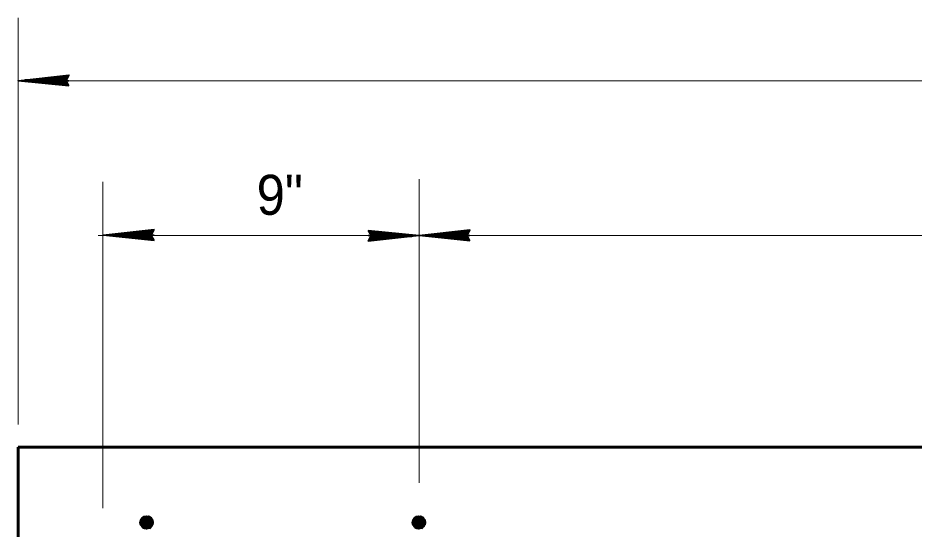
# Model space of a CAD drawing. Extents: x 6.34 to 9.53, y -1.46 to 0.53.
# Drawn here: x 6.7189 to 6.9057, y 0.195 to 0.3015 of the extents above; entities that cross this region are included whole.
import ezdxf
from ezdxf.enums import TextEntityAlignment as Align

# ---------------------------------------------------------------- set-up
doc = ezdxf.new("R2010")
doc.units = 0
doc.header["$LTSCALE"] = 0.0033
doc.layers.add('1', color=7, linetype='Continuous', lineweight=40)

msp = doc.modelspace()

# ---------------------------------------------------------------- linework, layer by layer
at = {"layer": '1', "lineweight": 13}
for p, q in [((6.718917, 0.216833), (6.718917, 0.3015)), ((6.718833, 0.288417), (7.301167, 0.288417)), ((6.736583, 0.199417), (6.736583, 0.267333)), ((6.8025, 0.204667), (6.8025, 0.267917)), ((6.735583, 0.256167), (7.2825, 0.256167)), ((6.718917, 0.212083), (6.718917, 0.212167))]:
    msp.add_line(p, q, dxfattribs=at)
at = {"layer": '1', "lineweight": 35}
for p, q in [((6.7295, 0.288417), (6.718917, 0.288417)), ((6.72925, 0.287583), (6.721417, 0.288583)), ((6.72925, 0.287583), (6.721417, 0.288417)), ((6.72925, 0.287417), (6.721417, 0.288333)), ((6.72925, 0.287417), (6.721417, 0.288333)), ((6.72925, 0.2875), (6.721417, 0.288333)), ((6.72925, 0.2895), (6.721917, 0.288667)), ((6.72925, 0.289333), (6.721917, 0.288583)), ((6.72925, 0.28925), (6.721917, 0.288417)), ((6.729333, 0.289083), (6.722, 0.288333)), ((6.74725, 0.25625), (6.736667, 0.25625)), ((6.747, 0.255417), (6.739167, 0.256417)), ((6.747, 0.255417), (6.739167, 0.25625)), ((6.747, 0.25525), (6.739167, 0.256167)), ((6.747, 0.25525), (6.739167, 0.256167)), ((6.747, 0.255333), (6.739167, 0.256167)), ((6.747, 0.257333), (6.739667, 0.2565)), ((6.747, 0.257167), (6.739667, 0.256417)), ((6.747, 0.257083), (6.739667, 0.25625)), ((6.747083, 0.256917), (6.73975, 0.256167)), ((6.791917, 0.256167), (6.8025, 0.256167)), ((6.792083, 0.2555), (6.799417, 0.25625)), ((6.792167, 0.257167), (6.8, 0.25625)), ((6.792167, 0.257167), (6.8, 0.25625)), ((6.792167, 0.257083), (6.8, 0.25625)), ((6.792167, 0.257), (6.8, 0.256167)), ((6.792167, 0.257), (6.8, 0.256)), ((6.792167, 0.255333), (6.7995, 0.256167)), ((6.792167, 0.25525), (6.7995, 0.256)), ((6.813083, 0.256167), (6.8025, 0.256167)), ((6.812833, 0.255333), (6.805, 0.256333)), ((6.812833, 0.255333), (6.805, 0.256167)), ((6.812833, 0.255167), (6.805, 0.256083)), ((6.812833, 0.255167), (6.805, 0.256083)), ((6.812833, 0.25525), (6.805, 0.256083)), ((6.812833, 0.25725), (6.8055, 0.256417)), ((6.812833, 0.257083), (6.8055, 0.256333)), ((6.812833, 0.257), (6.8055, 0.256167)), ((6.812917, 0.256833), (6.805583, 0.256083)), ((6.792167, 0.255083), (6.7995, 0.255917))]:
    msp.add_line(p, q, dxfattribs=at)
at = {"layer": '1', "lineweight": 60}
msp.add_line((6.718917, 0.212083), (7.30225, 0.212083), dxfattribs=at)
at = {"layer": '1'}
for p, q in [((6.74475, 0.195583), (6.745083, 0.1975)), ((6.744917, 0.1955), (6.74525, 0.1975)), ((6.744917, 0.1965), (6.746417, 0.196417)), ((6.744917, 0.196417), (6.746417, 0.196333)), ((6.744917, 0.196333), (6.746417, 0.19625)), ((6.744917, 0.19625), (6.746417, 0.196167)), ((6.744917, 0.196167), (6.746417, 0.196083)), ((6.745, 0.197583), (6.7465, 0.1975)), ((6.745, 0.1955), (6.745333, 0.1975)), ((6.745, 0.197417), (6.7465, 0.197333)), ((6.745, 0.197333), (6.7465, 0.19725)), ((6.745, 0.19725), (6.7465, 0.197167)), ((6.745, 0.197167), (6.7465, 0.197083)), ((6.745, 0.197083), (6.7465, 0.197)), ((6.745, 0.197), (6.7465, 0.196917)), ((6.745, 0.196917), (6.7465, 0.196833)), ((6.745, 0.196917), (6.7465, 0.196833)), ((6.745, 0.196833), (6.7465, 0.196667)), ((6.745, 0.196667), (6.7465, 0.1965)), ((6.745083, 0.1955), (6.7455, 0.1975)), ((6.745167, 0.1955), (6.745583, 0.1975)), ((6.745333, 0.1955), (6.745667, 0.197417)), ((6.745417, 0.195417), (6.74575, 0.197417)), ((6.7455, 0.195417), (6.745917, 0.197417)), ((6.745583, 0.195417), (6.746, 0.197333)), ((6.745667, 0.195417), (6.746083, 0.197333)), ((6.745833, 0.195333), (6.74625, 0.197333)), ((6.746083, 0.195333), (6.746417, 0.197333)), ((6.746167, 0.195333), (6.7465, 0.19725)), ((6.74625, 0.195333), (6.746583, 0.19725)), ((6.746333, 0.19525), (6.746667, 0.19725)), ((6.8015, 0.195583), (6.801833, 0.1975)), ((6.801667, 0.1955), (6.802, 0.1975)), ((6.801667, 0.1965), (6.803167, 0.196417)), ((6.801667, 0.196417), (6.803167, 0.196333)), ((6.801667, 0.196333), (6.803167, 0.19625)), ((6.801667, 0.19625), (6.803167, 0.196167)), ((6.801667, 0.196167), (6.803167, 0.196083)), ((6.80175, 0.197583), (6.80325, 0.1975)), ((6.80175, 0.1955), (6.802083, 0.1975)), ((6.80175, 0.197417), (6.80325, 0.197333)), ((6.80175, 0.197333), (6.80325, 0.19725)), ((6.80175, 0.19725), (6.80325, 0.197167)), ((6.80175, 0.197167), (6.80325, 0.197083)), ((6.80175, 0.197083), (6.80325, 0.197)), ((6.80175, 0.197), (6.80325, 0.196917)), ((6.80175, 0.196917), (6.80325, 0.196833)), ((6.80175, 0.196917), (6.80325, 0.196833)), ((6.80175, 0.196833), (6.80325, 0.196667)), ((6.80175, 0.196667), (6.80325, 0.1965)), ((6.801833, 0.1955), (6.80225, 0.1975)), ((6.801917, 0.1955), (6.802333, 0.1975)), ((6.802083, 0.1955), (6.802417, 0.197417)), ((6.802167, 0.195417), (6.8025, 0.197417)), ((6.80225, 0.195417), (6.802667, 0.197417)), ((6.802333, 0.195417), (6.80275, 0.197333)), ((6.802417, 0.195417), (6.802833, 0.197333)), ((6.802583, 0.195333), (6.803, 0.197333)), ((6.802833, 0.195333), (6.803167, 0.197333)), ((6.802917, 0.195333), (6.80325, 0.19725)), ((6.803, 0.195333), (6.803333, 0.19725)), ((6.803083, 0.19525), (6.803417, 0.19725)), ((6.744917, 0.196083), (6.746417, 0.196)), ((6.744917, 0.196), (6.746417, 0.195917)), ((6.744917, 0.195833), (6.746417, 0.19575)), ((6.744917, 0.19575), (6.746417, 0.195667)), ((6.744917, 0.195667), (6.746417, 0.195583)), ((6.744917, 0.195583), (6.746417, 0.1955)), ((6.744917, 0.1955), (6.746417, 0.195417)), ((6.801667, 0.196083), (6.803167, 0.196)), ((6.801667, 0.196), (6.803167, 0.195917)), ((6.801667, 0.195833), (6.803167, 0.19575)), ((6.801667, 0.19575), (6.803167, 0.195667)), ((6.801667, 0.195667), (6.803167, 0.195583)), ((6.801667, 0.195583), (6.803167, 0.1955)), ((6.801667, 0.1955), (6.803167, 0.195417))]:
    msp.add_line(p, q, dxfattribs=at)
at = {"layer": '1', "lineweight": 35}
for points in [[(6.7295, 0.287333), (6.718917, 0.288417), (6.7295, 0.289583), (6.728917, 0.288417)], [(6.72875, 0.288333), (6.724083, 0.28825), (6.724083, 0.288333), (6.725, 0.288333), (6.72875, 0.28825), (6.72575, 0.288167), (6.728917, 0.288083), (6.726667, 0.288), (6.728917, 0.287917), (6.725417, 0.288167), (6.72075, 0.288333), (6.721667, 0.288583), (6.720417, 0.288583), (6.72875, 0.288583), (6.726333, 0.28875), (6.728917, 0.28875), (6.723583, 0.288333), (6.728917, 0.289)], [(6.74725, 0.255167), (6.736667, 0.25625), (6.74725, 0.257417), (6.746667, 0.25625)], [(6.7465, 0.256167), (6.741833, 0.256083), (6.741833, 0.256167), (6.74275, 0.256167), (6.7465, 0.256083), (6.7435, 0.256), (6.746667, 0.255917), (6.744417, 0.255833), (6.746667, 0.25575), (6.743167, 0.256), (6.7385, 0.256167), (6.739417, 0.256417), (6.738167, 0.256417), (6.7465, 0.256417), (6.744083, 0.256583), (6.746667, 0.256583), (6.741333, 0.256167), (6.746667, 0.256833)], [(6.791917, 0.25725), (6.8025, 0.256167), (6.791917, 0.255), (6.7925, 0.256167)], [(6.792667, 0.25625), (6.797333, 0.256333), (6.797333, 0.25625), (6.796417, 0.25625), (6.792667, 0.256333), (6.795667, 0.256417), (6.7925, 0.2565), (6.79475, 0.256583), (6.7925, 0.256667), (6.796, 0.256417), (6.800667, 0.25625), (6.79975, 0.256), (6.801, 0.256), (6.792667, 0.256), (6.795083, 0.255833), (6.7925, 0.255833), (6.797833, 0.25625), (6.7925, 0.255583)], [(6.813083, 0.255083), (6.8025, 0.256167), (6.813083, 0.257333), (6.8125, 0.256167)], [(6.812333, 0.256083), (6.807667, 0.256), (6.807667, 0.256083), (6.808583, 0.256083), (6.812333, 0.256), (6.809333, 0.255917), (6.8125, 0.255833), (6.81025, 0.25575), (6.8125, 0.255667), (6.809, 0.255917), (6.804333, 0.256083), (6.80525, 0.256333), (6.804, 0.256333), (6.812333, 0.256333), (6.809917, 0.2565), (6.8125, 0.2565), (6.807167, 0.256083), (6.8125, 0.25675)]]:
    msp.add_lwpolyline(points, close=True, dxfattribs=at)
for points in [[(6.72875, 0.288333), (6.729167, 0.287583), (6.728917, 0.287833), (6.72875, 0.288167), (6.7285, 0.288083), (6.728667, 0.28775), (6.728833, 0.2885), (6.729, 0.289), (6.72925, 0.289417)], [(6.7465, 0.256167), (6.746917, 0.255417), (6.746667, 0.255667), (6.7465, 0.256), (6.74625, 0.255917), (6.746417, 0.255583), (6.746583, 0.256333), (6.74675, 0.256833), (6.747, 0.25725)], [(6.792667, 0.25625), (6.79225, 0.257), (6.7925, 0.25675), (6.792667, 0.256417), (6.792917, 0.2565), (6.79275, 0.256833), (6.792583, 0.256083), (6.792417, 0.255583), (6.792167, 0.255167)], [(6.812333, 0.256083), (6.81275, 0.255333), (6.8125, 0.255583), (6.812333, 0.255917), (6.812083, 0.255833), (6.81225, 0.2555), (6.812417, 0.25625), (6.812583, 0.25675), (6.812833, 0.257167)]]:
    msp.add_lwpolyline(points, dxfattribs=at)
at = {"layer": '1', "lineweight": 60}
msp.add_lwpolyline([(7.30225, 0.212083), (7.30225, 0.045417), (6.718917, 0.045417), (6.718917, 0.212083)], dxfattribs=at)
at = {"layer": '1'}
for points in [[(6.74575, 0.195083), (6.745417, 0.197667), (6.744917, 0.195333), (6.746, 0.197667), (6.746417, 0.19525), (6.74675, 0.19725), (6.744667, 0.19725), (6.747, 0.196333), (6.744417, 0.196583), (6.74675, 0.195583), (6.744417, 0.195917), (6.747, 0.19675), (6.74525, 0.195167), (6.745083, 0.197583), (6.746917, 0.195917), (6.7445, 0.197), (6.744917, 0.195333), (6.746417, 0.19525), (6.747, 0.196333), (6.74675, 0.19725), (6.746, 0.197667), (6.745083, 0.197583), (6.7445, 0.197), (6.745583, 0.196333), (6.7465, 0.1975), (6.74675, 0.195583), (6.745583, 0.196333), (6.745083, 0.19525), (6.744417, 0.19625), (6.7455, 0.196333), (6.74675, 0.197167), (6.7455, 0.195167), (6.745167, 0.1965), (6.744667, 0.19725)], [(6.8025, 0.195083), (6.802167, 0.197667), (6.801667, 0.195333), (6.80275, 0.197667), (6.803167, 0.19525), (6.8035, 0.19725), (6.801417, 0.19725), (6.80375, 0.196333), (6.801167, 0.196583), (6.8035, 0.195583), (6.801167, 0.195917), (6.80375, 0.19675), (6.802, 0.195167), (6.801833, 0.197583), (6.803667, 0.195917), (6.80125, 0.197), (6.801667, 0.195333), (6.803167, 0.19525), (6.80375, 0.196333), (6.8035, 0.19725), (6.80275, 0.197667), (6.801833, 0.197583), (6.80125, 0.197), (6.802333, 0.196333), (6.80325, 0.1975), (6.8035, 0.195583), (6.802333, 0.196333), (6.801833, 0.19525), (6.801167, 0.19625), (6.80225, 0.196333), (6.8035, 0.197167), (6.80225, 0.195167), (6.801917, 0.1965), (6.801417, 0.19725)]]:
    msp.add_lwpolyline(points, dxfattribs=at)
for centre in [(6.7457, 0.196417), (6.80245, 0.196417)]:
    msp.add_circle(centre, 0.00132, dxfattribs=at)

# ---------------------------------------------------------------- texts
at = {"layer": '1', "width": 0.95}
msp.add_text('9"', height=0.008334, dxfattribs=at).set_placement((6.773458, 0.2605), align=Align.CENTER)

doc.saveas('drawing.dxf')
